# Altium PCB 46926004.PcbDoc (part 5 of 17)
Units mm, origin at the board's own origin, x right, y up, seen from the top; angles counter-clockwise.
Board outline 250 x 200 mm, 6 copper layers (Top Layer, INT1_GND, INT2_SIG, INT3_SIG, INT4_GND, Bottom Layer), stack 1.71 mm thick; 1450 components, 1293 nets, 5656 pads, 2307 vias.
Unrouted connection lines stored in the file: 2.
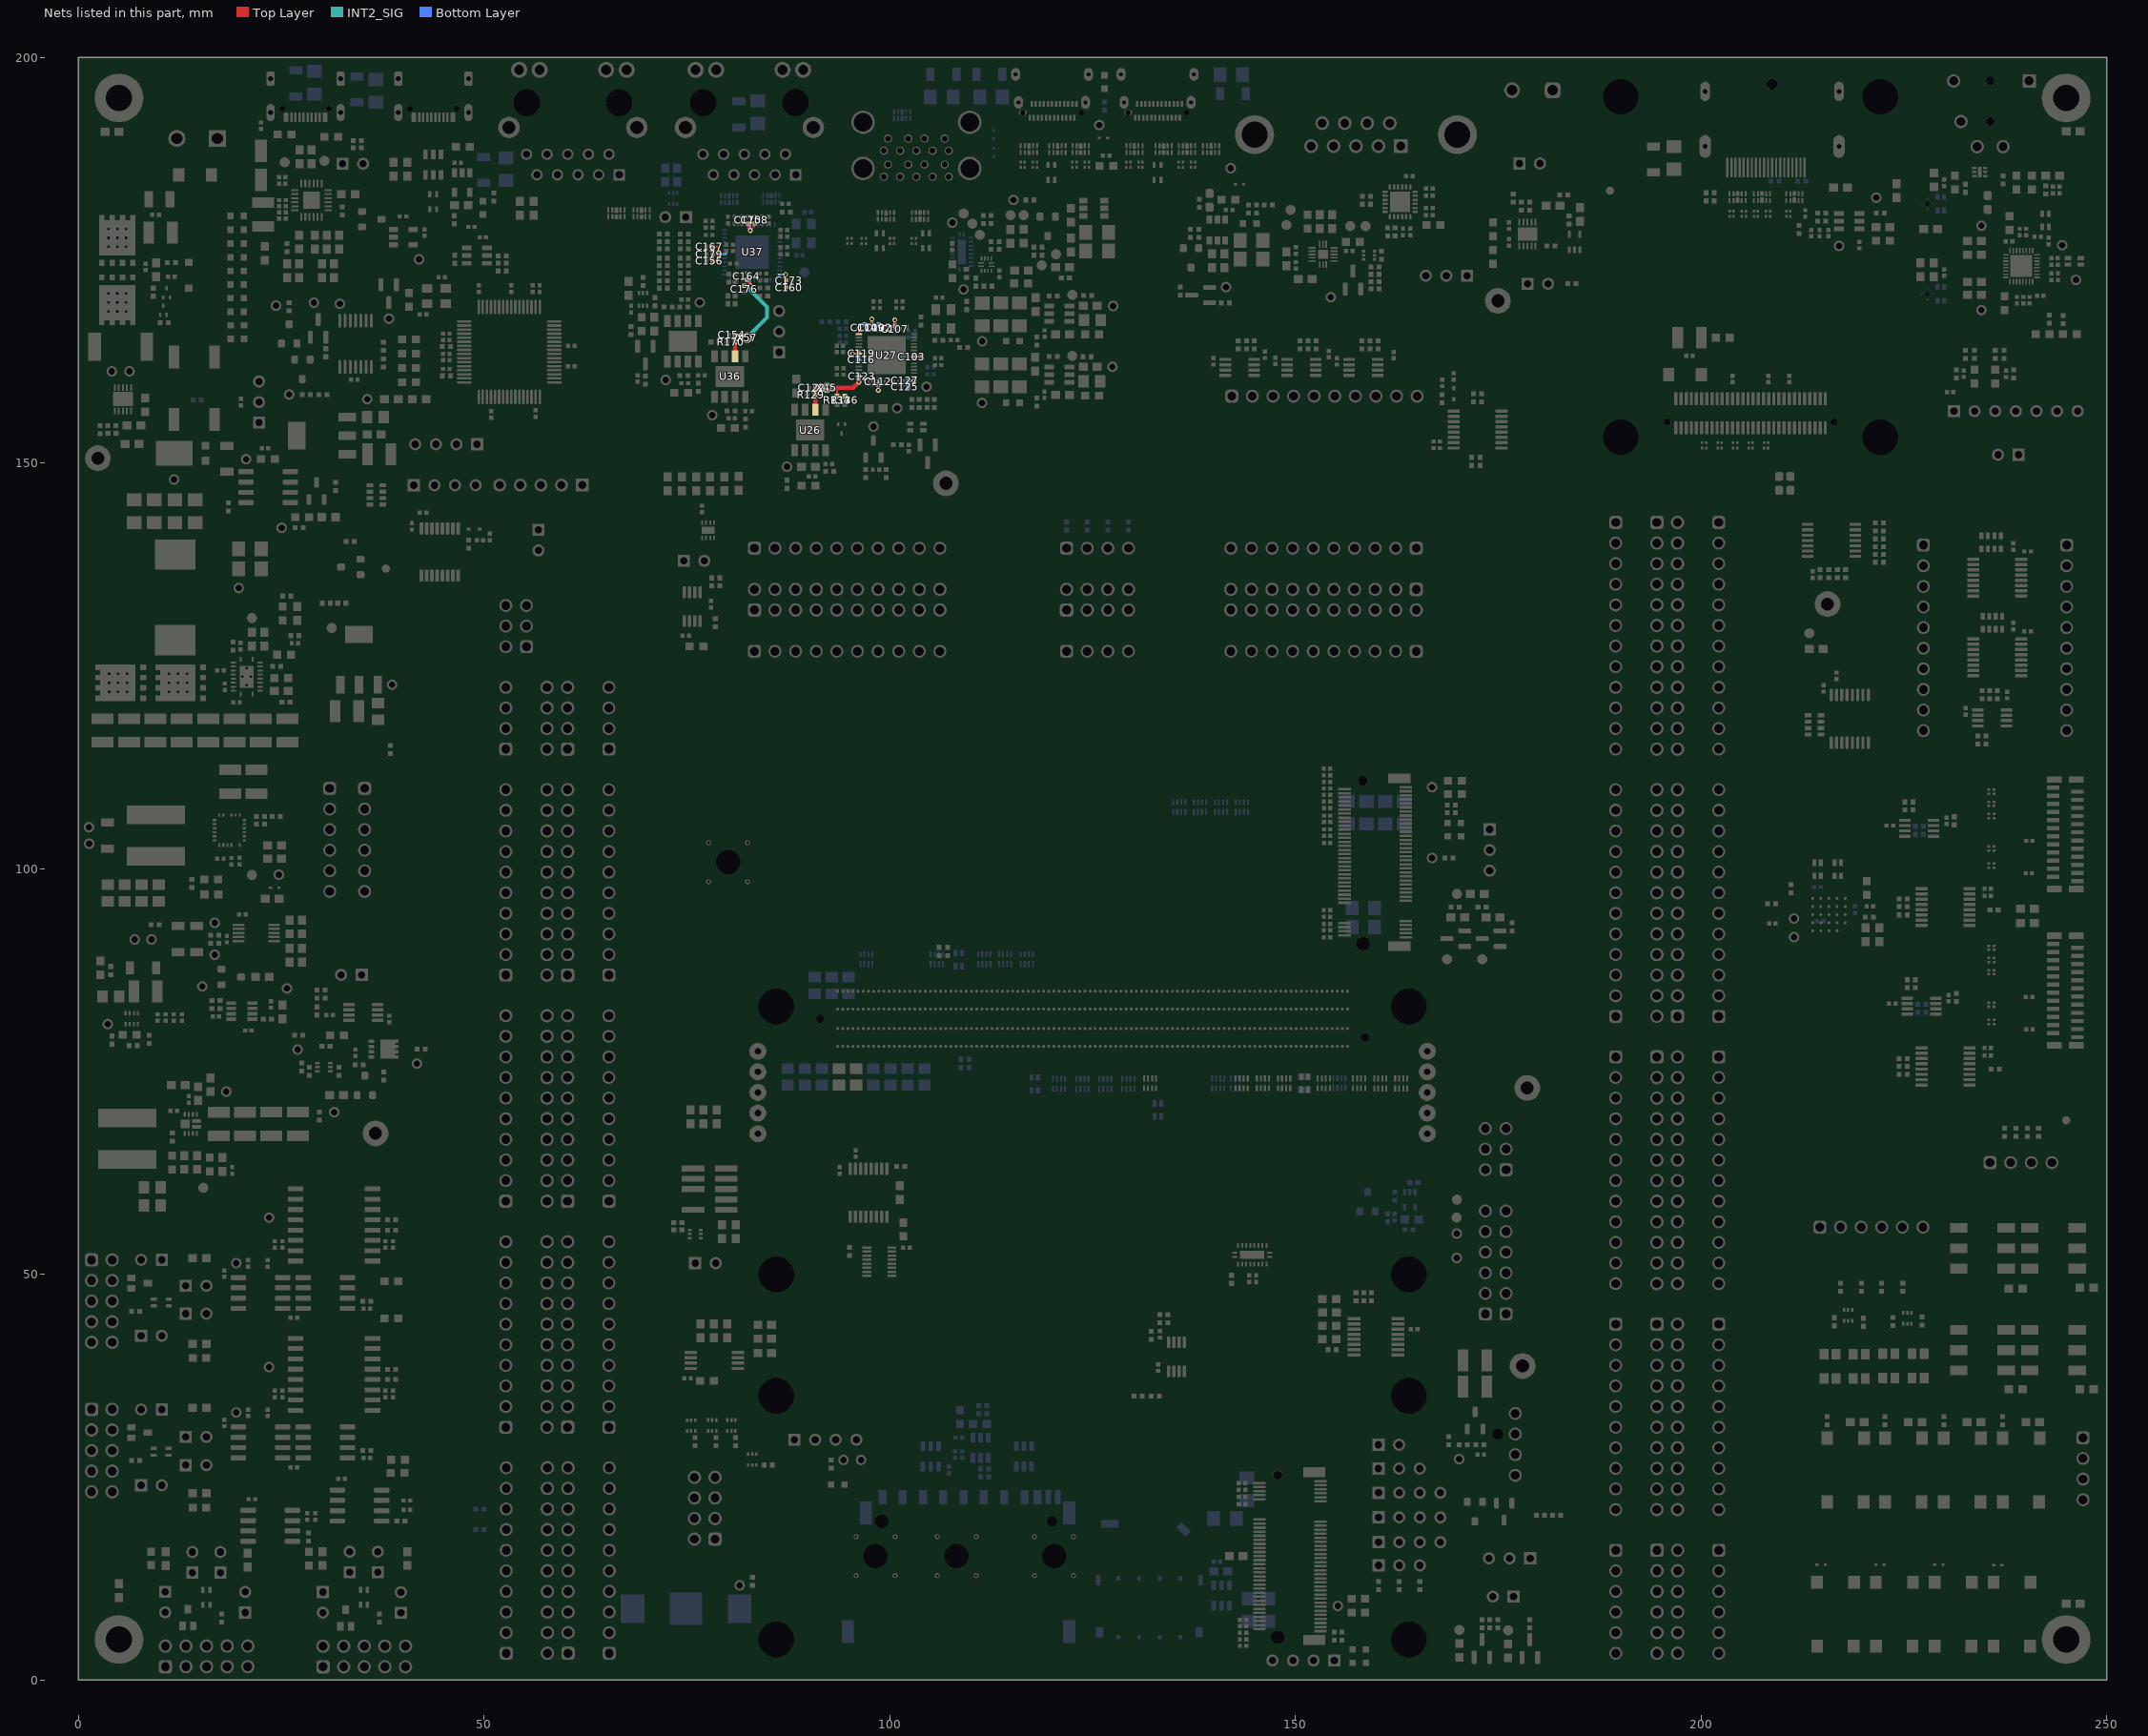
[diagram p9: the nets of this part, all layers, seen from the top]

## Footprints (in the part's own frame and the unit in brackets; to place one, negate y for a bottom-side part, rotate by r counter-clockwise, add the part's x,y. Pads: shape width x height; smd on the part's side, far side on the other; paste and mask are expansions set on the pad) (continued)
"VQFN-20 (3.5X4.5)" [mm] "RGY0020B, 20-VQFN (3.5x4.5)"
  rrect50% 0.25x0.6 smd paste+0 mask+0.051: 1(-0.75,2.15) 10(-0.75,-2.15) 11(0.75,-2.15) 20(0.75,2.15)
  rrect50% 0.6x0.25 smd paste+0 mask+0.051: 2(-1.65,1.75) 3(-1.65,1.25) 4(-1.65,0.75) 5(-1.65,0.25) 6(-1.65,-0.25) 7(-1.65,-0.75) 8(-1.65,-1.25) 9(-1.65,-1.75) 12(1.65,-1.75) 13(1.65,-1.25) 14(1.65,-0.75) 15(1.65,-0.25) 16(1.65,0.25) 17(1.65,0.75) 18(1.65,1.25) 19(1.65,1.75)
  round 0.6 hole 0.3 paste-2539.97 mask+0.051: 21(-0.55,0) 21(0,1.05) 21(0,-1.05) 21(0.55,0)
  rect 1.7x2.7 smd paste-1.337 mask+0.051: 21(0,0)
  silkscreen extent -1.95,-2.45 1.95,2.55, body extent -1.81,-2.31 1.81,2.31, height 1
"VQFN-20 (4.5X2.5)" [mm] "RKS0020A_TEX (2.50?4.50?1) 0.5-mm pitch"
  rrect50% 0.24x0.6 smd paste+0 mask+0.05: 1(-0.25,2.15) 10(-0.25,-2.15) 11(0.25,-2.15) 20(0.25,2.15)
  rrect50% 0.6x0.24 smd paste+0 mask+0.05: 2(-1.15,1.75) 3(-1.15,1.25) 4(-1.15,0.75) 5(-1.15,0.25) 6(-1.15,-0.25) 7(-1.15,-0.75) 8(-1.15,-1.25) 9(-1.15,-1.75) 12(1.15,-1.75) 13(1.15,-1.25) 14(1.15,-0.75) 15(1.15,-0.25) 16(1.15,0.25) 17(1.15,0.75) 18(1.15,1.25) 19(1.15,1.75)
  rect 1x3 smd paste-0.546 mask+0: 21(0,0)
  silkscreen extent -1.42,-2.43 1.42,2.84, body extent -1.3,-2.3 1.3,2.3, height 0.99
"VSONP-8 (5X6)" [mm] "8-PowerTDFN, DQJ0008A"
  rrect20% 0.75x0.675 smd paste+0 mask+0.051: 1(-2.753,1.905) 2(-2.753,0.635) 3(-2.753,-0.635) 4(-2.753,-1.905)
  rrect20% 0.75x0.675 smd paste-2539.97 mask+0.051: 5(2.753,-1.905) 6(2.753,-0.635) 7(2.753,0.635) 8(2.753,1.905)
  round 0.6 hole 0.3: 8(-0.772,1.1) 8(-0.772,-0.005) 8(-0.772,-1.1) 8(0.328,1.1) 8(0.328,-0.005) 8(0.328,-1.1) 8(1.428,-1.1) 8(1.428,-0.005) 8(1.428,1.1)
  rrect5% 4.35x4.485 smd paste-2.272 mask-2.273: 8(0.35,0)
  silkscreen extent -3.35,-2.47 3.4,2.47, body extent -3.1,-2.45 3.16,2.45, height 1.15
WE-CMS_9085 [mm] "Common Mode SMT Bead, body 9.00x8.50mm"
  rect 2.81x1.28 smd: 1(-3.85,2.5) 2(-3.85,-2.5) 3(3.85,-2.5) 4(3.85,2.5)
  silkscreen extent -4.7,-4.45 4.7,4.45, body extent -4.67,-4.25 4.67,4.25, height 4.63
WSON-8(2.1X2.1)_PAD [mm] "8-WFDFN Exposed Pad, 8-WSON (2x2), DSG0008A_TEX"
  rect 0.5x0.25 smd paste+0 mask+0: 1(-0.95,0.75) 2(-0.95,0.25) 3(-0.95,-0.25) 4(-0.95,-0.75) 5(0.95,-0.75) 6(0.95,-0.25) 7(0.95,0.25) 8(0.95,0.75)
  rect 0.9x1.6 smd paste-0.45 mask+0: 9(0,0)
  silkscreen extent -1.1,-1.15 1.07,1.4, body extent -1,-1 1,1, height 0.77
WURTH_9774080360R [mm]
  round 2.2 hole 4.4 unplated: 0(0,0)
  Top Layer circle w1.3: c0,0 r3.05
  Top Layer keep-out circle w0.05: c0,0 r3.9
  Bottom Layer keep-out circle w0.05: c0,0 r2.45
  silkscreen extent -4,-4 4,4, body extent -2.92,-2.95 3.08,3.04, height 8
WURTH_61300411821 [mm] "Socket Header, Pitch 2.54 mm, THT, Vertical, single row, 4p"
  rrect50% 1.6x1.6 hole 1.1: 1(-3.81,0)
  round 1.6 hole 1.1: 2(-1.27,0) 3(1.27,0) 4(3.81,0)
  silkscreen extent -5.46,-1.35 5.46,1.35, body extent -5.33,-1.25 5.33,1.25, height 8.55
WURTH_61300611821 [mm] "Socket Header, Pitch 2.54 mm, THT, Vertical, single row, 6p"
  rrect50% 1.6x1.6 hole 1.1: 1(-6.35,0)
  round 1.6 hole 1.1: 2(-3.81,0) 3(-1.27,0) 4(1.27,0) 5(3.81,0) 6(6.35,0)
  silkscreen extent -8,-1.35 8,1.35, body extent -7.87,-1.25 7.87,1.25, height 8.55
WURTH_61300621821 [mm] "Socket Header, Pitch 2.54 mm, THT, Vertical, dual row, 6p"
  rrect50% 1.6x1.6 hole 1.1: 1(-2.54,-1.27)
  round 1.6 hole 1.1: 2(-2.54,1.27) 3(0,-1.27) 4(0,1.27) 5(2.54,-1.27) 6(2.54,1.27)
  silkscreen extent -4.19,-2.62 4.19,2.62, body extent -4.06,-2.54 4.06,2.54, height 8.45
WURTH_61300821121 [mm] "Pin Header, pitch 2.54 mm, THT, Vertical, dual row, 8p"
  rrect50% 1.65x1.65 hole 1.1: 1(-3.81,-1.27)
  round 1.65 hole 1.1: 2(-3.81,1.27) 3(-1.27,-1.27) 4(-1.27,1.27) 5(1.27,-1.27) 6(1.27,1.27) 7(3.81,-1.27) 8(3.81,1.27)
  silkscreen extent -5.81,-2.62 5.23,2.62, body extent -5.08,-2.54 5.08,2.54, height 8.59
WURTH_61301011821 [mm] "Socket Header, Pitch 2.54 mm, THT, Vertical, single row, 10p"
  rrect50% 1.6x1.6 hole 1.1: 1(-11.43,0)
  round 1.6 hole 1.1: 2(-8.89,0) 3(-6.35,0) 4(-3.81,0) 5(-1.27,0) 6(1.27,0) 7(3.81,0) 8(6.35,0) 9(8.89,0) 10(11.43,0)
  silkscreen extent -13.08,-1.35 13.08,1.35, body extent -12.95,-1.25 12.95,1.25, height 8.55
WURTH_61301021121 [mm] "Pin Header, pitch 2.54 mm, THT, Vertical, dual row, 10p"
  rrect50% 1.65x1.65 hole 1.1: 1(-5.08,-1.27)
  round 1.65 hole 1.1: 2(-5.08,1.27) 3(-2.54,-1.27) 4(-2.54,1.27) 5(0,-1.27) 6(0,1.27) 7(2.54,-1.27) 8(2.54,1.27) 9(5.08,-1.27) 10(5.08,1.27)
  silkscreen extent -6.5,-2.62 6.5,2.62, body extent -6.35,-2.54 6.35,2.54, height 8.59
WURTH_61301211821 [mm] "Socket Header, Pitch 2.54 mm, THT, Vertical, single row, 12p"
  rrect50% 1.6x1.6 hole 1.1: 1(-13.97,0)
  round 1.6 hole 1.1: 2(-11.43,0) 3(-8.89,0) 4(-6.35,0) 5(-3.81,0) 6(-1.27,0) 7(1.27,0) 8(3.81,0) 9(6.35,0) 10(8.89,0) 11(11.43,0) 12(13.97,0)
  silkscreen extent -15.62,-1.35 15.62,1.35, body extent -15.49,-1.25 15.49,1.25, height 8.55
WURTH_61301221121 [mm] "Pin Header, pitch 2.54 mm, THT, Vertical, dual row, 12p"
  rrect50% 1.65x1.65 hole 1.1: 1(-6.35,-1.27)
  round 1.65 hole 1.1: 2(-6.35,1.27) 3(-3.81,-1.27) 4(-3.81,1.27) 5(-1.27,-1.27) 6(-1.27,1.27) 7(1.27,-1.27) 8(1.27,1.27) 9(3.81,-1.27) 10(3.81,1.27) 11(6.35,-1.27) 12(6.35,1.27)
  silkscreen extent -8.35,-2.62 7.77,2.62, body extent -7.62,-2.54 7.62,2.54, height 8.59
WURTH_61302021121 [mm] "Pin Header, pitch 2.54 mm, THT, Vertical, dual row, 20p"
  rrect50% 1.65x1.65 hole 1.1: 1(-11.43,-1.27)
  round 1.65 hole 1.1: 2(-11.43,1.27) 3(-8.89,-1.27) 4(-8.89,1.27) 5(-6.35,-1.27) 6(-6.35,1.27) 7(-3.81,-1.27) 8(-3.81,1.27) 9(-1.27,-1.27) 10(-1.27,1.27) 11(1.27,-1.27) 12(1.27,1.27) 13(3.81,-1.27) 14(3.81,1.27) 15(6.35,-1.27) 16(6.35,1.27) 17(8.89,-1.27) 18(8.89,1.27) 19(11.43,-1.27) 20(11.43,1.27)
  silkscreen extent -13.43,-2.62 12.85,2.62, body extent -12.7,-2.54 12.7,2.54, height 8.59
WURTH_61302421121 [mm] "Pin Header, pitch 2.54 mm, THT, Vertical, dual row, 24p"
  rrect50% 1.65x1.65 hole 1.1: 1(-13.97,-1.27)
  round 1.65 hole 1.1: 2(-13.97,1.27) 3(-11.43,-1.27) 4(-11.43,1.27) 5(-8.89,-1.27) 6(-8.89,1.27) 7(-6.35,-1.27) 8(-6.35,1.27) 9(-3.81,-1.27) 10(-3.81,1.27) 11(-1.27,-1.27) 12(-1.27,1.27) 13(1.27,-1.27) 14(1.27,1.27) 15(3.81,-1.27) 16(3.81,1.27) 17(6.35,-1.27) 18(6.35,1.27) 19(8.89,-1.27) 20(8.89,1.27) 21(11.43,-1.27) 22(11.43,1.27) 23(13.97,-1.27) 24(13.97,1.27)
  silkscreen extent -15.95,-2.62 15.39,2.62, body extent -15.24,-2.54 15.24,2.54, height 8.59
WURTH_691137710002 [mm] "Horizontal Cable Entry with Pressure Clamp, pitch 5mm, 02p"
  rrect50% 1.95x1.95 hole 1.3: 1(-2.5,0.25)
  round 1.95 hole 1.3: 2(2.5,0.25)
  silkscreen extent -5,-3.36 5,3.75, body extent -5,-3.75 5,3.75, height 11.6
XTAL_CX3225 [mm] "KYOCERA"
  rect 1.3x1.05 smd mask+0.08: 1(-1.15,-0.925) 2(1.15,-0.925) 3(1.15,0.925) 4(-1.15,0.925)
  silkscreen extent -2.11,-1.73 0.2,1.47, body extent -1.6,-1.25 1.6,1.25, height 1.05

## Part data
B1 B2 B3 B4 B5 B6 B7 B8: library part "1511-Push Button", "(-25 to 70 DegC) SWITCH TACTILE SPST-NO 0.05A 24V H:4.3mm Switch-PushButton", Mfr=Omron, Supplier Part Number 1=SW1440CT-ND
C1 C2 C18 C19 C20 C23 C40 C43 C205 C265 C266 C272 C273 C274 C275 C278 C281 C284 C293 C331 C332: library part 1607-Cap-1206-10uF/50V, "(-55 to 85 DegC) CAP CER 10UF 50V 10% X5R 1206", Mfr=Samsung, MfrNo=CL31A106KBHNNNE, Supplier Part Number 1=1276-2876-1-ND
C3 C5 C7 C8 C9 C10 C11 C12 C17 C29 C34 C47 C48 C65 C66 C67 C68 C69 C70 C74 C78 C79 C80 C83 C84 C85 C86 C87 C88 C89 C91 C92 C93 C97 C99 C100 C107 C109 C111 C112 C113 C114 C115 C116 C117 C118 C119 C120 C123 C129 C130 C131 C132 C133 C134 C135 C136 C137 C138 C144 C145 C146 C147 C155 C170 C171 C172 C173 C174 C175 C176 C178 C179 C182 C188 C192 C193 C194 C195 C196 C197 C200 C201 C202 C203 C204 C206 C207 C208 C209 C210 C211 C212 C217 C218 C219 C223 C224 C228 C229 C231 C232 C233 C234 C235 C236 C237 C238 C239 C240 C241 C242 C243 C244 C245 C246 C249 C250 C251 C252 C254 C256 C259 C260 C261 C262 C270 C276 C286 C287 C292 C294 C296 C297 C301 C302 C303 C304 C305 C306 C307 C308 C309 C310 C311 C312 C313 C314 C315 C316 C317 C318 C319 C320 C321 C322 C323 C324 C326 C328 C333 C342 C345 C350 C351 C352 C353 C354 C356 C357 C358 C359 C360 C381 C382 C387 C388 C389 C390 C392 C394: library part 1566-Cap-0402-100nF/50V, "(-55 to 125 DegC AEC) Cap Ceramic 0.1uF 50V X7R 10% 0402", Mfr=Murata, MfrNo=GRT155R71H104KE01D, Supplier Part Number 1=490-GRT155R71H104KE01DCT-ND
C4 C13 C14 C15 C52 C53 C54 C55 C56 C57 C58 C59 C60 C61 C62 C63 C64 C285: "(-55 to 85 DegC) CAP CER 22uF 16V X5R 0805", Mfr=Samsung, MfrNo=CL21A226MOQNNNE, Supplier Part Number 1=1276-2909-1-ND
C6 C268: "(-55 to 125 DegC AEC) CAP CER 1.5nF 10% 50V X7R 0402", Mfr="Taiyo Yuden", MfrNo=UMK105B7152KVHF, Supplier Part Number 1=587-6365-1-ND
C16: library part 0665-Cap-0603-470pF/50V, "(-55 to 125 DegC) CAP CER 470PF 50V NP0 0603", Mfr="Samsung Electro-Mechanics America, Inc.", MfrNo=CL10C471JB8NNNC, Supplier Part Number 1=1276-1168-1-ND
C21 C22 C24 C25 C26 C39 C41 C72 C73 C75 C76 C82 C90 C108 C110 C122 C149 C150 C151 C152 C153 C154 C247 C248 C253 C255 C257 C258 C347: library part 2404-Cap-0402-22uF/6.3V, "(-55 to 85 DegC) CAP CER 22UF 6.3V 20% X5R 0402", Mfr=Murata, MfrNo=GRM155R60J226ME11D, Supplier Part Number 1=C415703
C27 C289: library part 1149-Cap-0402-10nF/50V, "(-55 to 125 DegC) Cap Ceramic 10nF 50V X7R 10% 0402", Mfr=Yageo, MfrNo=CC0402KRX7R9BB103, Supplier Part Number 1=311-1349-2-ND
C28 C32 C33 C190 C191 C198 C199 C325 C343 C344: library part 2282-Cap-1206-100uF/10V, "(-55 to 85 DegC) CAP CER 100UF 10V 20% X5R 1206", Mfr=Murata, MfrNo=GRM31CR61A107MEA8L, Supplier Part Number 1=490-GRM31CR61A107MEA8LCT-ND
C30: "(-55 to 85 DegC) CAP CER 10UF 16V 10% X5R 0603", Mfr=Murata, MfrNo=GRM21BR61C106KE15L, Supplier Part Number 1=490-3886-1-ND
C31 C35 C355: "(-55 to 85 DegC) CAP CER 4.7UF 10V 20% X5R 0603", Mfr=Samsung, MfrNo=CL10A475KP8NNNC, Supplier Part Number 1=1276-1044-1-ND
C36 C121 C124 C125 C127: "(-55 to 125 DegC) CAP CER 1000PF 50V 5% NP0 0402", Mfr="Samsung Electro-Mechanics America, Inc", MfrNo=CL05C102JB5NNNC, Supplier Part Number 1=1276-1635-1-ND
C37 C277: "(-55 to 125 DegC AEC) Cap Ceramic 47pF 100V C0G/NP0 5% SMD 0603", Mfr=Samsung, MfrNo=CL10C470JC81PNC, Supplier Part Number 1=1276-6563-1-ND
C38 C339 C340: "(-55 to 125 DegC) CAP CER 220PF 50V 5% NP0 0603", Mfr=Samsung, MfrNo=CL10C221JB8NCNC, Supplier Part Number 1=1276-2234-1-ND
C42 C44 C45 C46: "(-55 to 85 DegC) CAP CER 47UF 10V X5R 0805", Mfr=Murata, MfrNo=GRM21BR61A476ME15L, Supplier Part Number 1=490-9961-1-ND
C49 C141 C142 C158 C160 C161 C164 C165 C166 C167 C168 C169 C213 C214 C295 C298 C334: "(-55 to 85 DegC) CAP CER 1UF 16V 20% X5R 0402", Mfr=Murata, MfrNo=GRM155R61C105MA12D, Supplier Part Number 1=490-14599-1-ND
C50 C98: "Cap 0603 DNP"
C51 C139 C140: library part 1314-Cap-0805-22uF/16V, "(-55 to 85 DegC) CAP CER 22uF 16V X5R 0805", Mfr=Samsung, MfrNo=CL21A226MOQNNNE, Supplier Part Number 1=1276-2909-1-ND
C71 C101 C148 C186 C288 C329 C330 C346: "(-55 to 125 DegC) CAP CER 1000PF 2KV X7R 1206", Mfr="Johanson Dielectrics Inc.", MfrNo=202R18W102KV4E, Supplier Part Number 1=709-1036-1-ND
C77 C81: "(-55 to 125 DegC AEC) CAP CER 20PF 5% 50V C0G/NPO 0402", Mfr=Samsung, MfrNo=CL05C200JB51PNC, Supplier Part Number 1=1276-6601-1-ND
C94 C96 C102 C103 C104 C105 C106 C220 C221 C222 C230 C280 C282 C327 C348 C349: "(-55 to 85 DegC) CAP CER 4.7UF 6.3V 20% X5R 0402", Mfr="Murata Electronics North America", MfrNo=GRM155R60J475ME87D, Supplier Part Number 1=490-5408-1-ND
C95 C225 C226 C227 C271: "(-55 to 85 DegC) CAP CER 2.2UF 10V 20% X5R 0402", Mfr=Yageo, MfrNo=CC0402MRX5R6BB225, Supplier Part Number 1=311-1733-1-ND
C126 C128 C159 C162 C177 C267: "(-55 to 125 DegC AEC) CAP CER 30PF 5% 50V C0G/NPO 0402", Mfr=Murata, MfrNo=GCM1555C1H300JA16D, Supplier Part Number 1=490-GCM1555C1H300JA16DCT-ND
C143 C156 C157 C163 C335 C337 C365 C366 C367 C368 C369 C374 C375 C376 C377 C378 C379 C380 C385 C386 C391 C393: "(-55 to 85 DegC) CAP CER 10UF 6.3V 20% X5R 0402", Mfr=Murata, MfrNo=GRM155R60J106ME44D, Supplier Part Number 1=490-13811-2-ND
C180 C181 C183 C185 C187 C283: "(-55 to 85 DegC) CAP CER 47UF 10V 20% X5R 1206", Mfr=Samsung, MfrNo=CL31A476MPHNNNE, Supplier Part Number 1=1276-3063-1-ND
C184 C189 C336 C338 C341: "(-55 to 125 DegC) CAP CER 470PF 50V NP0 0603", Mfr="Samsung Electro-Mechanics America, Inc.", MfrNo=CL10C471JB8NNNC, Supplier Part Number 1=1276-1168-1-ND
C215 C216 C263 C264: "(-55 to 125 DegC) CAP CER 3600PF 50V C0G/NP0 0603", Mfr=Murata, MfrNo=GRM1885C1H362JA01D, Supplier Part Number 1=490-6386-1-ND
C269: "(-55 to 125 DegC) CAP CER 0.047UF 50V X7R 0603", Mfr="TDK Corporation", MfrNo=C1608X7R1H473K080AA, Supplier Part Number 1=445-1313-1-ND
C279: "(-55 to 125 DegC) CAP CER 560PF 25V C0G/NPO 0603", Mfr=Yageo, MfrNo=CC0603JRNPO8BN561, Supplier Part Number 1=311-3957-1-ND
C290 C291: "(-55 to 125 DegC) CAP CER 330PF 100V 5% NP0 0603", Mfr=Samsung, MfrNo=CL10C331JC8NNNC, Supplier Part Number 1=1276-2274-1-ND
C299 C300: "(-55 to 85 DegC AEC) CAP CER 1UF 50V X7R 0603", Mfr=Murata, MfrNo=GRT188R61H105ME13D, Supplier Part Number 1=490-12331-1-ND
C361 C362 C363 C364 C370 C371 C372 C373 C383 C384: "(-55 to 85 DegC) CAP CER 100UF 6.3V X5R 1206", Mfr=Yageo, MfrNo=CC1206MKX5R5BB107, Supplier Part Number 1=311-1991-1-ND
D1 D31: library part 0434-SMAJ28CA, "(-55 to 150 DegC) TVS DIODE 28VWM 59VC SMA", Mfr=STMicroelectronics, MfrNo=SMAJ28CA-TR, Supplier Part Number 1=497-4620-1-ND
D2 D24 D34: library part "1859-LED Red 0603", "(-30 to 85 DegC) LED RED 0603 99mcd Vf:2.0V", Mfr="Vishay Lite-On", MfrNo=LTST-C190KRKT, Supplier Part Number 1=160-1436-1-ND
D3: library part 2201-SDT15H50P5-13, "(-55 to 150 DegC) DIODE SCHOTTKY 15A 50V Vf:0.3V@1.5A 0.47V@15A SMA", Mfr=Diodes, Supplier Part Number 1=31-SDT15H50P5-13CT-ND
D4 D5 D6 D7 D9 D11 D14 D18 D20 D21 D25 D26 D29 D30 D45 D48 D49: library part "0333-LED Green 0603", "(-40 to 85 DegC) LED GREEN 0603 50mcd", Mfr=Kingbright, MfrNo=APT1608CGCK, Supplier Part Number 1=754-1116-1-ND
D8 D15 D33 D35 D36 D37 D38 D43 D50: library part 1655-D5V0L1B2S9-7, "(-65 to 155 DegC) TVS DIODE Vwm:5V Vcl:14V@6A SOD-923", Mfr=Diodes, Supplier Part Number 1=D5V0L1B2S9-7DICT-ND
D10 D13: library part 1670-BAT54XV2T5G, "(-55 to 125 DegC) DIODE SCHOTTKY 30V 200MA SOD523 / SC79", Mfr="ON Semiconductor", Supplier Part Number 1=BAT54XV2T5GOSCT-ND
D12 D16 D17 D19 D22 D23 D27 D28 D32 D47: library part 0242B-BAT54C, "(-55 to 125 DegC) DIODE SCHOTTKY 30V 200MA SOT23, comm. Cathode", Mfr="ON Semi", MfrNo=BAT54CLT1G, Supplier Part Number 1=BAT54CLT1GOSCT-ND
D39 D40 D41 D42: library part 1775-ASMB-MTB0-0B3A2, "(-40 to 100 DegC) LED RGB DIFFUSED 4PLCC SMD", Mfr=Broadcom, Supplier Part Number 1=516-ASMB-MTB0-0B3A2CT-ND
D44: library part 0210-BZX84-C12, "(-65 to 150 DegC) DIODE ZENER 12V 225MW SOT23-3", Mfr="On Semi", MfrNo=BZX84C12LT1G, Supplier Part Number 1=BZX84C12LT1GOSCT-ND
D46: library part 1159-1N4148W, "(-55 to 150 DegC) DIODE GEN PURP 100V 300MA SOD123", Mfr=Diodes, MfrNo=1N4148W-7-F, Supplier Part Number 1=1N4148W-FDICT-ND
F1: library part "2200-Fuse 15A 1206 Slow", "(-55 to 90 DegC) FUSE BOARD MOUNT 15A 63VDC SLOW", Mfr=Schurter, MfrNo=3413.0330.22, Supplier Part Number 1=693-3413.0330.22
F2: library part "1336-Fuse 7A Slow", "(-55 to 125 DegC) FUSE SLOW 63VDC 6A 1206 14.5mohm", Mfr=Bel, MfrNo=0685T6000-01, Supplier Part Number 1=507-2300-1-ND
FID1 FID2 FID3 FID4 FID5 FID6: library part 0000-Fiducial-round, "Fiducial round d=1.0mm"
H1 H2 H3 H4: library part 000-Hole-125mil
J1 J2 J3 J5 J7 J9 J12: library part "2203-Conn-Hdr 2x10 2.54MM", "(-40 to 105 DegC) CONN HEADER MALE VERT 2x10 20POS 2.54MM TH", Mfr="Wurth Electronics", Supplier Part Number 1=732-5301-ND
J1A J1B J2A J2B J3A J3B J5A J5B J7A J7B J9A J9B J12A J12B J13 J60 J61: library part "2202-Conn-Hdr 1x10 2.54MM F", "(-40 to 105 DegC) CONN HEADER FEMALE VERT 1x10 10POS 2.54MM TH", Mfr="Wurth Electronics", Supplier Part Number 1=732-2859-ND
J4 J6 J8: library part "2206-Conn-Hdr 2x12 2.54MM", "(-40 to 105 DegC) CONN HEADER MALE VERT 2x12 24POS 2.54MM TH", Mfr="Wurth Electronics", Supplier Part Number 1=710-61302421121
J4A J4B J6A J6B J8A J8B: library part "2221-Conn-Hdr 1x12 2.54MM F", "(-40 to 105 DegC) CONN HEADER FEMALE VERT 1x12 12POS 2.54MM TH", Mfr="Wurth Electronics", Supplier Part Number 1=710-61301211821
J10 J11 J19: library part "2532-Conn-Hdr 2x4 2.54MM", "(-40 to 105 DegC) CONN HEADER MALE VERT 2x4 8POS 2.54MM TH", Mfr="Wurth Electronics", Supplier Part Number 1=732-5296-ND
J10A J10B J11A J11B J50 J53: library part "2191-Conn-Hdr 1x4 2.54MM F", "(-40 to 125 DegC) CONN HEADER FEMALE 1x4 4POS 2.54MM TH", Mfr="Wurth Electronics", Supplier Part Number 1=732-61300411821-ND
J14: library part "2266-Conn-Hdr 2x6 2.54MM", "(-40 to 105 DegC) CONN HEADER MALE VERT 2x6 12POS 2.54MM TH", Mfr="Wurth Electronics", Supplier Part Number 1=732-5297-ND
J14A J14B J15 J16 J55 J94 J96: library part "2189-Conn-Hdr 1x6 2.54MM F", "(-40 to 125 DegC) CONN HEADER FEMALE 1x6 6POS  2.54MM TH", Mfr="Wurth Electronics", Supplier Part Number 1=732-61300611821-ND
J17: library part "1610-Conn 2-POS R/A", "(-40 to 100 DegC) TERM BLOCK HDR 2POS R/A 90DEG TH 5MM 300V/16A", Mfr="Phoenix Contact", Supplier Part Number 1=277-14388-ND
J18: "(-40 to 85 DegC) CONN HDR VERT 1x2 2pos 2.54mm 0.1in Gold no-shroud", Mfr="Amphenol FCI", MfrNo=67996-200HLF, Supplier Part Number 1=609-5098-1-ND
J20: library part "2094-Conn-Hdr 1x2 2POS 5MM SCREW TERM", "(-30 to 120 DegC) CONN TERM BLK 2POS SIDE ENTRY 5MM SCREW 16A 300V", Mfr="Wurth Electronics", Supplier Part Number 1=732-10955-ND
J21 J87 J91: library part "2539-Conn-Hdr-1x3 TH Vert", "(-65 to 125 DegC) CONN HDR VERT 3x1 3pos 2.54mm 0.1in Gold no-shroud", Mfr="Amphenol ICC / FCI", Supplier Part Number 1=649-68001-203HLF
J22 J28 J31 J51 J88: "Header, 2-Pin"
J23 J65: library part 1660-Conn-USB-Type-C, "(-40 to 85 DegC) Conn USB TYPE C RA, 24 (16+8 Dummy) Position, SMT/TH", Mfr="Global Connector Technology", Supplier Part Number 1=2073-USB4105-GF-A-120CT-ND
J24 J26 J37 J38 J40 J54 J57: "Header, 4-Pin"
J25: "Header, 5-Pin"
J27: library part 2274-CONN-DISPLAY-PORT, "(-20 to 85 DegC) CONN RCPT DISPLAYPORT 20P SMD RA/TH", Mfr=Molex, MfrNo=47272-0001, Supplier Part Number 1=538-47272-0001
J29 J45 J49 J58 J63 J64 J66 J68 J73 J74 J75 J76 J79 J80 J81 J82 J85 J86 J89 J90 J92: library part "1250-Conn-Hdr-1x2 TH Vert", "(-40 to 85 DegC) CONN HDR VERT 1x2 2pos 2.54mm 0.1in Gold no-shroud", Mfr="Amphenol FCI", Supplier Part Number 1=609-5098-1-ND
J30: library part 2184-Conn-SD, "(-40 to 85 DegC) CONN SD CARD PUSH-PULL R/A, OPEN", Mfr="Same Sky", Supplier Part Number 1=2223-SD-4-BCT-ND
J32 J72: library part 1512-Conn-USB-Type-C, "(-40 to 85 DegC) Conn USB TYPE C RA SMT", Mfr="Amphenol Communications Solutions", Supplier Part Number 1=12401826E412ACT-ND
J33: library part 1820-Conn-USB3-2x-RA, "(-40 to 85 DegC) Conn USB 3.1 Type A R/A TH", Mfr="Amphenol Commercial", Supplier Part Number 1=GSB4112312HR-ND
J34 J36: library part 1380-Conn-RJ45-GBe, "(-40 to 85 DegC) CONN MAGJACK 1PORT 1000 BASE-T Isolated Taps", Mfr=Pulse, Supplier Part Number 1=1840-1005-ND
J35 J41 J52 J62: "Header, 3-Pin"
J39: library part 2186-Conn-M2-KeyB, "(-40 to 80 DegC) CONN M2 M.2 Key B 67pos H=2.75mm Gold", Mfr="Amphenol Commercial", Supplier Part Number 1=523-MDT275B03001
J42: "(-40 to 85 DegC) CONN MICRO SIM CARD PUSH-PULL", Mfr="Molex, LLC", MfrNo=0787231001, Supplier Part Number 1=WM9259CT-ND
J43: library part 2461-Conn-M2-KeyM_4.2mm, "(-40 to 85 DegC) CONN M.2 KEYM FMALE 67POS 0.020 GOLD 4.2MM HEIGHT", Mfr="Amphenol Communications Solutions", Supplier Part Number 1=649-MDT420M01501
J44: library part 1462-Conn-SelfMate-60pin, "(-55 to 125 DegC) CONN SELF-MATE 60POS SMD GOLD", Mfr=Samtec, Supplier Part Number 1=612-LSS-130-03-L-DV-A-K-TRCT-ND
J46: library part 1840-Conn-Audio-Jack-5pos-3.5mm, "(-20 to 85 DegC) CONN JACK STEREO 3.5MM 5pos TipSwitch TH R/A", Mfr="Same Sky", Supplier Part Number 1=CP-43515TS-ND
J47 J48: library part "2193-Conn-Hdr 2x3 2.54MM F", "(-40 to 125 DegC) CONN HEADER FEMALE 2x3 6POS 2.54MM TH", Mfr="Wurth Electronics", Supplier Part Number 1=732-61300621821-ND
J56: library part "2220-Conn-Hdr 4POS 2.54MM", "(-40 to 80 DegC) CONN HEADER VERT 4POS 2.54MM - 1 Wall Shrouded", Mfr=Molex, MfrNo=47053-1000, Supplier Part Number 1=WM4330-ND
J59: "(-55 to 125 DegC) CONN HEADER VERT 9POS 2x5 1.27MM JTAG", Mfr=Samtec, MfrNo=FTSH-105-01-L-DV-007-K, Supplier Part Number 1=SAM9438-ND
J67: library part "0760-Conn-DSUB9 Male R/A", "(-55 to 105 DegC) CONN D-SUB PLUG 9POS R/A SOLDER Male", Mfr="Assmann WSW Components", MfrNo="A-DS 09 A/KG-T2S", Supplier Part Number 1=AE10968-ND
J69: "Header, 7-Pin"
J70 J71: library part 1461-Conn-FFC-24pin-0.5mm-Vert, "(-40 to 85 DegC) CONN FFC VERT 24POS 0.50MM SMD", Mfr=Hirose, Supplier Part Number 1=H125143CT-ND
J77 J78 J83 J84: library part "2237-Conn-Hdr 2x10 2.54MM", "(-40 to 105 DegC) CONN HEADER MALE VERT 2x5 10POS 2.54MM TH", Mfr="Wurth Electronics", Supplier Part Number 1=732-2672-ND
J95 J97: library part "2368-Conn-POGO 1x5 2.54MM", "CONN SPRING PISTON 5POS PCB 2.54MM TH", Mfr=Mill-Max, Supplier Part Number 1=ED8201-05-ND
JP1 JP2 JP3 JP4: library part 000-Jumper-Short, "Jumper Wire"
L1: library part 2226-Ind-9x8.5-83ohm/21A-Choke, "(-40 to 125 DegC AEC) CMC Choke 21A 83OHM 9x8.5x4.8mm DCR = 3mohm", Mfr="Wurth Electronics", MfrNo=7427523, Supplier Part Number 1=710-7427523
L4 L6: library part 1845-Ind-8x8x5-4.7uH/11A, "(-40 to 85 DegC) FIXED IND 4.7UH 11A Is:13A 14 mohm typ, 15.4 moh max SMD 8.4x8x5 full-shield", Mfr="Eaton Bussmann", Supplier Part Number 1=283-EXL1V0705-4R7-RCT-ND
L5: "(-40 to 125 DegC) FIXED IND 1UH I:5.5A Isat:6.5A 32mohm max 26mohm typ, full-shield SMD 1210", Mfr=Bourns, MfrNo=SRP3212-1R0M, Supplier Part Number 1=118-SRP3212-1R0MCT-ND
L9: "(-50 to 150 DegC) FIXED IND 2.2UH 22A 4.2 mOHM 13.5x12.5x6.4mm", Mfr=Bourns, MfrNo=SRP1265A-2R2M, Supplier Part Number 1=652-SRP1265A-2R2M
L10 L11 L12 L43 L45: "(-55 to 125 DegC) FERRITE BEAD 5 OHM @ 100MHz 0402 0.5A DCR:80mohm", Mfr=Murata, MfrNo=BLM15BB050SN1D, Supplier Part Number 1=490-5185-1-ND
L13 L15 L16 L17 L18 L19 L20 L21 L26 L31 L32 L33 L41 L42 L46 L47 L48 L49 L55 L56 L57 L60 L61 L62 L63 L66 L71 L72 L75 L78 L79 L80 L91 L92: "(-55 to 125 DegC) FERRITE BEAD 330 OHM 0603 1.7A 80mohm, typ 48mohm", Mfr="TDK Corporation", MfrNo=MPZ1608S331ATA00, Supplier Part Number 1=445-5221-1-ND
L14 L30 L36 L39 L99: library part 0277-Ind-2x1.2-90ohm/0.4A-Choke, "(-40 to 125 DegC) INDUCTOR COMMON MODE 90 OHM 0.4A 0.3ohm", Mfr="Bourns Inc.", MfrNo=SRF2012-900YA, Supplier Part Number 1=SRF2012-900YACT-ND
L22 L23 L28 L29 L34 L35 L37 L38 L50 L51 L52 L53 L54 L76 L81 L82 L83 L84 L85 L86 L87 L88 L89 L90 L94 L95 L96 L97 L100 L101 L102 L103: library part 1371-Ind-0.8x0.6-12ohm/0.1A-Choke, "(-40 to 85 DegC) Ind CMC Choke 12 Ohm 0.1A 1ohm 0.85x0.65x0.5mm", Mfr=Panasonic, MfrNo=EXC-14CH120U, Supplier Part Number 1=P19438CT-ND
L58 L59 L73 L74: library part 1055-Ind-2x1.2-220ohm/0.4A-Choke, "(-40 to 125 DegC) INDUCTOR COMMON MODE 220 OHM 0.3A 0.4ohm", Mfr="Bourns Inc.", MfrNo=SRF2012-221YA, Supplier Part Number 1=SRF2012-221YACT-ND
L77: "(-55 to 125 DegC AEC) FERRITE BEAD 42ohm 10A 0.75mohm 3x3mm SMD", Mfr="Laird Steward", MfrNo=35F0121-0SR-10, Supplier Part Number 1=240-2520-1-ND
LBL1: library part 000-Label-0.25x0.9IN, "Label for Toradex serial number label 0.25x0.9 inch"
M1: library part 2421-Conn-Toradex-Aquila, "(-55 to 125 DegC) CONN AcceleRate HD APM6 0.635MM 400POS SMD HIGH DENSITY ARRAY, 5MM STACK HEIGHT (UN-BALLED)", Mfr=Samtec
ME1 ME2 ME3 ME4: library part 0989-Post-M3-8mm, "(-55 to 150 DegC) ROUND STANDOFF M3X0.5 STEEL 8MM For Apalis", Mfr="Wurth Electronics Inc.", Supplier Part Number 1=732-5275-1-ND
ME5 ME6 ME7 ME8 ME9 ME10 ME11 ME12: "(-55 to 155 DegC) ROUND STANDOFF M3X0.5 BRASS 5MM", Mfr=Sinhoo, MfrNo=SMTSO3050CTJ, Supplier Part Number 1=C2915636
ME13 ME14 ME15 ME18: library part 1855-Post-M2-0.5mm, "(-55 to 155 DegC) ROUND STANDOFF M2X0.4 STEEL 0.5MM", Mfr="Wurth Electronics", Supplier Part Number 1=732-9774005243RCT-ND
MP1 MP2 MP3 MP4 MP5 MP6 MP7 MP8 MP9 MP10: library part 1476-Bumper-10mmD-6mmH, "(-40 to 85 DegC) Bumper Polyurethane, D: 9.5mm, H: 6.3mm, adhesive", Mfr=3M, Supplier Part Number 1=SJ5749-0-ND
Q1 Q2 Q23: library part 2195-CSD18511Q5A, "(-55 to 150 DegC) MOSFET N-CH 40V 27A Vth:1.8V Ron typ:3.5mohm@4.5V Vgsm:2.45V 8-VSONP (5x6)", Mfr="Texas Instruments", MfrNo=CSD18511Q5AT, Supplier Part Number 1=595-CSD18511Q5AT
Q3: library part 1858-DMP26M7UFG-7, "(-55 to 150 DegC) MOSFET P-CH 20V 18A 4.2mohm@4.5V 7mohm@1.8V Vgsm:10V 3x3mm POWERDI3333", Mfr=Diodes, Supplier Part Number 1=DMP26M7UFG-7DICT-ND
Q4 Q5 Q6 Q8 Q21 Q28 Q29: library part 0761-FDV301N, "(-55 to 155 DegC) MOSFET N-CH 25V 220MA SOT-23 Vth:1.1V Ron typ:4ohm@3V Vgsm:8V", Mfr="Fairchild/ON Semiconductor", Supplier Part Number 1=FDV301NCT-ND
Q7 Q30: library part 1674-NTZD3155CT1G, "(-40 to 85 DegC) MOSFET N/P-CH 20V 0.54/0.43A Vgs:1V SOT-563", Mfr="ON Semiconductor", Supplier Part Number 1=NTZD3155CT1GOSCT-ND
Q9 Q10 Q11 Q12 Q15 Q18 Q19 Q31 Q32: library part 1146-NTZD3154NT1G, "(-55 to 150 DegC) MOSFET 2N-CH (dual) 20V 0.54A SOT-563 1.6x1.6mm Vth:1V Ron typ:400m@4.5V, 500m@2.5V, 700m@1.8V", Mfr="ON Semiconductor", MfrNo=NTZD3154NT1G, Supplier Part Number 1=NTZD3154NT1GOSCT-ND
Q13: library part 0186-DMP3099L, "(-55 to 150 DegC) MOSFET P-CH 30V 3.8A 65mohm SOT23", Mfr="Diodes Incorporated", MfrNo=DMP3099L-7, Supplier Part Number 1=DMP3099L-7DICT-ND
Q14 Q16 Q25: library part 1857-MMBT5551M3T5G, "(-55 to 150 DegC) TRANS NPN 160V 60mA 1.2x1.2 SOT723", Mfr="ON Semiconductor", Supplier Part Number 1=MMBT5551M3T5GOSCT-ND
Q17: library part 0910-IRLML0040TRPBF, "(-55 to 150 DegC) MOSFET N-CH 40V 3.6A SOT-23-3 Ron typ 60mohm@5V, ---@3V", Mfr="Infineon Technologies", MfrNo=IRLML0040TRPBF, Supplier Part Number 1=IRLML0040TRPBFCT-ND
Q22: library part 2196-CSD18503Q5A, "(-55 to 150 DegC) MOSFET N-CH 40V 19A Vth:1.8V Ron typ:4.3mohm@10V Vgsm:2.45V 8-VSONP (5x6)", Mfr="Texas Instruments", Supplier Part Number 1=595-CSD18503Q5A
Q24: "(-55 to 150 DegC) MOSFET 2P-CH 30V 9.2A 8SO", Mfr="Infineon Technologies", MfrNo=IRF9358TRPBF, Supplier Part Number 1=942-IRF9358TRPBF
Q26 Q27: library part 0030-2N7002, "(-55 to 150 DegC AEC) MOSFET N-CH SGL 60V SOT-23 0.3A 1.3ohm@5V", Mfr=NXP, MfrNo=2N7002P,215, Supplier Part Number 1=568-5818-1-ND
R1 R389: "(-55 to 155 DegC AEC) RES 887K OHM 1% 1/16W 100ppm 0402", Mfr="Stackpole Electronics", MfrNo=RMCF0402FT887K
R2 R6 R44 R49 R142 R143 R309: "(-55 to 155 DegC) RES SMD 24.9K OHM 1% 1/10W 0603 100ppm", Mfr="Stackpole Electronics", MfrNo=RMCF0603FT24K9, Supplier Part Number 1=RMCF0603FT24K9CT-ND
R3 R7 R46 R303 R304 R310 R311 R323 R326 R336: "(-55 to 155 DegC) RES SMD 20K 1% 1/10W 0603 100ppm", Mfr=Bourns, MfrNo=CR0603-FX-2002ELF, Supplier Part Number 1=CR0603-FX-2002ELFCT-ND
R4 R19 R20 R29 R30 R31 R36 R45 R55 R86 R87 R89 R90 R104 R114 R129 R134 R165 R166 R182 R193 R195 R198 R203 R283 R285 R335 R378 R379: "(-55 to 155 DegC AEC) RES 27K OHM 1% 1/16W 100ppm 0402", Mfr="Stackpole Electronics", MfrNo=RMCF0402FT27K0, Supplier Part Number 1=RMCF0402FT27K0CT-ND
R5 R9 R35 R37 R53 R56 R57 R63 R115 R256 R257 R259 R261 R263 R270 R289 R290 R307 R317 R344 R360 R361 R362 R366 R368 R369 R370 R374 R375 R376 R377 R391 R393 R394 R399 R404 R434: "(-55 to 155 DegC) RES 100K OHM 1/16W 1% 0402 SMD", Mfr=Yageo, MfrNo=RC0402FR-07100KL, Supplier Part Number 1=311-100KLRCT-ND
R8: "(-55 to 170 DegC AEC) RES 0.003 OHM 1% 2W 2512 50ppm", Mfr=Bourns, MfrNo=CRF2512-FZ-R003ELF, Supplier Part Number 1=652-CRF2512FZR003ELF
R10 R27 R43 R50 R58 R59 R67 R68 R95 R108 R113 R116 R117 R118 R122 R135 R136 R137 R152 R154 R162 R169 R171 R173 R181 R186 R188 R189 R215 R218 R230 R231 R238 R266 R268 R269 R271 R273 R274 R279 R280 R281 R282 R313 R314 R327 R332 R333 R334 R343 R345 R352 R358 R382 R383 R384 R385 R408 R418 R419 R432 R453 R454 R455 R456 R457 R459 R460 R470 R473 R474 R476: "(-55 to 155 DegC AEC) RES 10K OHM 1% 1/16W 100ppm 0402", Mfr="Stackpole Electronics", MfrNo=RMCF0402FT10K0, Supplier Part Number 1=RMCF0402FT10K0CT-ND
R11 R15 R17 R28 R32 R33 R38 R54 R64 R110 R131 R183 R185 R194 R199 R217 R221 R222 R223 R228 R232 R233 R234 R251 R252 R287 R301 R308 R329 R331 R337 R339 R341 R354 R355 R359 R367 R406 R435 R436 R437 R438 R447 R448 R449 R463 R464: "(-55 to 155 DegC) RES 0.0 OHM 1/10W JUMP 0603", Mfr=Samsung, MfrNo=RC1608J000CS, Supplier Part Number 1=1276-3510-1-ND
R12 R69 R70 R77 R100 R126 R127 R248 R363 R371: "(-55 to 155 DegC AEC) RES 200K OHM 1% 1/16W 100ppm 0402", Mfr="Stackpole Electronics", MfrNo=RMCF0402FT200K, Supplier Part Number 1=RMCF0402FT200KCT-ND
R13 R14 R24 R26 R40 R60 R71 R72 R73 R74 R78 R79 R83 R102 R103 R119 R144 R145 R172 R174 R239 R249 R250 R272 R312 R364 R365 R372 R373 R387 R396 R402 R403 R430 R431 R445 R446 R465: "(-55 to 155 DegC) RES 4.70K OHM 1/16W 1% 0402 100ppm", Mfr=Yageo, MfrNo=RC0402FR-074K7L, Supplier Part Number 1=311-4.7KLRCT-ND
R16 R18 R34 R96 R106 R107 R109 R124 R138 R139 R180 R191 R224 R225 R226 R229 R235 R236 R237 R253 R254 R284 R286 R288 R320 R321 R328 R330 R338 R342 R346 R386 R390 R407 R439: "RES 0603"
R21 R25 R348 R349 R353: "(-55 to 155 DegC) RES 10 OHM 1/16W 1% 0402 SMD", Mfr="Rohm Semiconductor", MfrNo=MCR01MRTF10R0, Supplier Part Number 1=RHM10.0CDCT-ND
R22 R23 R51: "(-55 to 150 DegC) RES CURRENT SENSE .010 OHM 1W 1% 50ppm", Mfr=Ohmite, MfrNo=MCS1632R010FER, Supplier Part Number 1=MCS1632R010FERCT-ND
R39: "RES CURRENT SENSE .010 OHM 1W 1% 50ppm", Mfr=Ohmite, MfrNo=MCS1632R010FER, Supplier Part Number 1=MCS1632R010FERCT-ND
R41 R42 R48: "(-55 to 155 DegC) RES SMD 220K OHM 1% 1/10W 0603", Mfr=Yageo, MfrNo=RC0603FR-07220KL, Supplier Part Number 1=311-220KHRCT-ND
R47 R324 R452: "(-55 to 155 DegC AEC) RES 15K OHM 1% 1/16W 100ppm 0402", Mfr="Stackpole Electronics", MfrNo=RMCF0402FT15K0, Supplier Part Number 1=RMCF0402FT15K0CT-ND
R52 R75 R76 R88 R99 R175 R187 R196 R197 R202 R204 R227 R264 R265 R409 R410 R411 R412 R413 R414 R426 R427 R442 R443 R468 R469 R471 R472 R477 R478: "(-55 to 155 DegC AEC) RES 1.87K OHM 1% 1/16W 100ppm 0402", Mfr="Stackpole Electronics", MfrNo=RMCF0402FT1K87, Supplier Part Number 1=RMCF0402FT1K87CT-ND
R61 R84 R325: "(-55 to 155 DegC) RES 300K OHM 1/10W 1% 0603 SMD", Mfr=Yageo, MfrNo=RC0603FR-07300KL, Supplier Part Number 1=311-300KHRCT-ND
R62 R65 R66 R125 R128 R140 R141 R149 R150 R151 R158 R161 R164 R167 R168 R184 R200 R219 R322 R392 R417 R450 R451 R475: "RES 0402"
R80 R81 R315 R388 R405: "(-55 to 155 DegC) RES 5.1K OHM 1/10W 1% 0603 SMD", Mfr=Rohm, MfrNo=MCR03ERTF5101, Supplier Part Number 1=RHM5.10KCFCT-ND
R82 R120 R148 R179 R267 R319 R397 R398: "(-55 to 155 DegC) RES SMD 1M OHM 5% 0.25W 10ppm 1206", Mfr="TE Connectivity", MfrNo=CRGCQ1206J1M0, Supplier Part Number 1=A130195CT-ND
R85 R97 R98 R190 R241 R243 R245 R247 R275 R276 R277 R278 R440 R441 R444: "(-55 to 155 DegC AEC) RES 86.6K OHM 1% 1/16W 100ppm 0402", Mfr="Stackpole Electronics", MfrNo=RMCF0402FT86K6, Supplier Part Number 1=RMCF0402FT86K6CT-ND
R91 R132 R306: "(-55 to 155 DegC AEC) RES 12K OHM 1% 1/16W 100ppm 0402", Mfr="Stackpole Electronics", MfrNo=RMCF0402FT12K0, Supplier Part Number 1=RMCF0402FT12K0CT-ND
R92 R93 R94 R458 R467: "(-55 to 155 DegC AEC) RES 1M OHM 1% 1/16W 100ppm 0402", Mfr="Stackpole Electronics", MfrNo=RMCF0402FT1M00, Supplier Part Number 1=RMCF0402FT1M00CT-ND
R101 R112: "(-55 to 155 DegC) RES SMD 2K OHM 1% 1/10W 0603 100ppm", Mfr=Yageo, MfrNo=RC0603FR-072KL, Supplier Part Number 1=311-2.00KHRCT-ND
R105 R111 R121 R123 R159 R160 R210 R213 R220 R298 R350 R356 R357 R380 R381 R395 R400 R401 R433: "(-55 to 155 DegC AEC) RES 120 OHM 1% 1/16W 100ppm 0402", Mfr="Stackpole Electronics", MfrNo=RMCF0402FT120R, Supplier Part Number 1=RMCF0402FT120RCT-ND
R130: "(-55 to 155 DegC) RES 56K OHM 1/10W 1% 0603", Mfr="Samsung Electro-Mechanics America, Inc", MfrNo=RC1608F563CS, Supplier Part Number 1=1276-4816-1-ND
R133 R291 R292 R316 R351: "(-55 to 155 DegC AEC) RES 1K OHM 1% 1/16W 100ppm 0402", Mfr="TE Connectivity", MfrNo=CRGCQ0402F1K0, Supplier Part Number 1=A129627CT-ND
R146 R147 R177 R178 R240 R242 R244 R246 R255 R258 R260 R262: "(-55 to 155 DegC) RES 510 OHM 1/10W 1% 0603 SMD", Mfr=Yageo, MfrNo=RC0603FR-07510RL, Supplier Part Number 1=311-510HRCT-ND
R153 R155 R157 R163 R170: "(-55 to 155 DegC) RES SMD 2.49K OHM 1% 1/16W 0402 100ppm", Mfr=Yageo, MfrNo=RC0402FR-072K49L, Supplier Part Number 1=311-2.49KLRCT-ND
R156: "(-55 to 155 DegC) RES 5.76K OHM 1/16W 1% 0402 SMD", Mfr="Stackpole Electronics", MfrNo=RMCF0402FT5K76, Supplier Part Number 1=RMCF0402FT5K76CT-ND
R176: "(-55 to 155 DegC AEC) RES SMD 11K OHM 1% 1/16W 0402 100ppm 0402", Mfr=Yageo, MfrNo=AC0402FR-0711KL, Supplier Part Number 1=YAG3439CT-ND
R192 R212 R214 R297 R299 R300 R302 R340: "RES 0.0 OHM 1/10W JUMP 0603", Mfr=Samsung, MfrNo=RC1608J000CS, Supplier Part Number 1=1276-3510-1-ND
R205 R206 R207 R208 R293 R294 R295 R296: "(-55 to 155 DegC) RES SMD 60.4 OHM 1% 1/10W 0603", Mfr=Bourns, MfrNo=CR0603-FX-60R4ELF, Supplier Part Number 1=652-CR0603FX-60R4ELF
R216: "(-55 to 155 DegC) RES 2.20K OHM 1/10W 1% 0603 SMD", Mfr=Yageo, MfrNo=RC0603FR-072K2L, Supplier Part Number 1=311-2.20KHRCT-ND
R305: "(-55 to 155 DegC) RES SMD 240 OHM 1% 1/16W 0402", Mfr=Yageo, MfrNo=RC0402FR-07240RL, Supplier Part Number 1=311-240LRCT-ND
R318 R347: "(-55 to 155 DegC AEC) RES 330 OHM 1% 1/16W 100ppm 0402", Mfr="Stackpole Electronics", MfrNo=RMCF0402FT330R
R420 R421 R422 R423: "(-55 to 155 DegC AEC) RES 5.6K OHM 1% 1/16W 100ppm 0402", Mfr=Yageo, MfrNo=RC0402FR-075K6L, Supplier Part Number 1=311-5.6KLRCT-ND
R461 R462: "(-55 to 155 DegC) RES SMD 22 OHM 1% 1/16W 0402", Mfr=Murata, MfrNo=GRT155R71H104KE01D
RA1 RA15 RA17 RA29 RA35 RA37 RA41: "(-55 to 125 DegC) RES ARRAY 2 RES 22 OHM 5% 0606 200ppm", Mfr=Panasonic, MfrNo=EXB-34V220JV, Supplier Part Number 1=Y8220CT-ND
RA3 RA8 RA9 RA10: "(-55 to 125 DegC) RES ARRAY 4 RES 10K 1% 200ppm 1206", Mfr=Yageo, MfrNo=TC164-FR-0710KL, Supplier Part Number 1=RAVF164DJT10K0CT-ND
RA4 RA5 RA6: "RES ARRAY 2 RES 0606"
RA7 RA11 RA14 RA16 RA18 RA19 RA20 RA21 RA22 RA23 RA24 RA25 RA26 RA27 RA28 RA30 RA31 RA32 RA33 RA34 RA36 RA38 RA39 RA40 RA45: "(-55 to 125 DegC) RES ARRAY 4 RES 22 OHM 0804 +/-300ppm SMD", Mfr=Bourns, MfrNo=CAT10A-220J4LF, Supplier Part Number 1=118-CAT10A-220J4LFCT-ND
S1 S2 S3 S4: library part "2693-Slide Switch-DPDT VERT SMT", "(-20 to 70 DegC) Slide switch DPDT 12V 100mA SMT 9.1x6.9mm VERT SLIDE", Mfr="Same Sky (CUI)", Supplier Part Number 1=2223-SLW-913535-2A-SMTCT-ND
U1 U104: library part 1666-MCP1799, "(-40 to 150 DegC) IC REG LINEAR LDO Vin: 45Vmax Vout:5V fixed 80mA SOT223-3", Mfr=Microchip, MfrNo=MCP1799T-5002H/DB, Supplier Part Number 1=150-MCP1799T-5002H/DBCT-ND
U2: library part 2224-LTC4368IDD-2#PBF, "(-40 to 85 DegC AEC) IC SURGE SUPPRESSION ADJ 2.5-60V OVERVOLTAGE/UNDERVOLTAGE/OVERCURRENT PROTECT 10DFN", Mfr="Analog Devices / Linear Technology", Supplier Part Number 1=584-LTC4368IDD2PBF
U3 U9 U10 U11 U19 U57 U81 U83 U88: library part 0972-PCA9306DCT, "(-40 to 85 DegC) IC TRANSLTR BIDIRECTIONAL I2C SM8", Mfr="Texas Instruments", MfrNo=PCA9306DCTR, Supplier Part Number 1=296-18509-1-ND
U4: library part 0966-INA226AIDGSR, "(-40 to 125 DegC) IC MONITOR PWR/CURR BIDIR 10MSOP I2C Vos:10uV max, 0.1%Gain Err max, 2.7-5.5Vcc, 0-36V", Mfr="Texas Instruments", MfrNo=INA226AIDGSR, Supplier Part Number 1=296-29034-1-ND
U5: library part 1619-TPS62823, "(-40 to 125 DegC) IC  IC REG BUCK ADJ 2.2MHz Vin:2.4-5.5V Io:3A Sync 8-VFDFN 8VSON-HR", Mfr="Texas Instruments", Supplier Part Number 1=296-50425-1-ND
U6: library part 1815-AOZ2261AQI-15, "(-40 to 85 DegC) 8A Syncronous Buck Regulator (Auto Restart), QFN4x4-22L, 4-28V", Mfr="Alpha & Omega Semiconductor", Supplier Part Number 1=785-1930-1-ND
U7: library part 2218-TPS61089RNRR, "(-40 to 85 DegC) IC REG BOOST ADJ 7A SYNC 20VQFN Vin:2.7-12V, Vout:4.5-12.6V 11VQFN", Mfr="Texas Instruments", Supplier Part Number 1=296-47295-1-ND
U8: library part 2192-LTC2954CTS8-2#TRMPBF, "(0 to 70 DegC) IC PB ON/OFF CONTROLLER TSOT23-8", Mfr="Analog Devices / Linear Technology", Supplier Part Number 1=505-LTC2954CTS8-2#TRMPBFCT-ND
U12 U17 U18 U42: library part 0740-TPD4E001, "(-40 to 125 DegC AEC) TVS DIODE 5.5VWM 16VC SOT-23-6", Mfr="Texas Instruments", MfrNo=TPD4E001QDBVRQ1, Supplier Part Number 1=296-39344-1-ND
U13: library part 0968-AP2127K, "(-40 to 85 DegC) IC REG LIN LDO POS ADJ 300MA (450 max) SOT23-5 2.5-6 Vin 0.3Vd@0.3A", Mfr="Diodes Incorporated", MfrNo=AP2127K-ADJTRG1, Supplier Part Number 1=AP2127K-ADJTRG1DICT-ND
U14: library part 1263-93LC56BT, "(-40 to 85 DegC) IC EEPROM 2KBit 128x16 SPI 2MHz SOT23-6 2.5-5.5V", Mfr=Microchip, Supplier Part Number 1=93LC56BT-I/OTCT-ND
U15: library part 0956-FT4232H, "(-40 to 85 DegC) IC USB HS QUAD UART/SYNC 64-LQFP", Mfr="FTDI, Future Technology Devices International Ltd", MfrNo=FT4232HL-REEL, Supplier Part Number 1=768-1026-2-ND
U16 U28 U29 U80: library part 1475-AP22653, "(-40 to 85 DegC) IC PWR SWITCH 3-5.5V EN-Active-High ENth:1.5V With-Discharge 65mohm typ ADJ 0.1-2.1A 6SSOP", Mfr=Diodes, Supplier Part Number 1=31-AP22653AW6-7CT-ND
U20 U23 U24 U30 U31 U32 U33 U34 U38 U39 U46 U47 U53 U84 U98 U99 U100: library part 1463-D3V3F4U10LP, "(-55 to 150 DegC) IC TVS DIODE 4ch Vrm:3.3V Vbr:6.2 Vcl:5V@16A 12KV/12KV 0.5pF 10-UFDFN 0.5mm", Mfr=Diodes, Supplier Part Number 1=D3V3F4U10LP-7DICT-ND
U21 U97: library part 2238-AP22615AWU-7, "(-40 to 85 DegC) IC PWR SWITCH 3-5.5V EN-Active-High ENth:1.2V With-Discharge 40mohm typ ADJ 0.4-4A TSOT-26", Mfr=Diodes, Supplier Part Number 1=AP22615AWU-7DICT-ND
U22: library part 1831-PTN5110, "(-40 to 85 DegC) IC USB Type-C CC Logic and port control DRP 16-HX2QFN 2.6x2.6", Mfr="NXP Semiconductors", Supplier Part Number 1=568-13797-1-ND
U25 U40: library part 2239-PESD15VL2BT,215, "(-65 to 150 DegC) TVS DIODE 2-CH 15VWM 44VC ESD:30KV TO236AB", Mfr=Nexperia, Supplier Part Number 1=1727-3813-1-ND
U26 U35 U36: library part 1467-AP2132BMP-2.5, "(-40 to 85 DegC) IC REG LDO LINEAR POS ADJ 5V 2A 8SO", Mfr=Diodes, Supplier Part Number 1=AP2132BMP-2.5TRG1DICT-ND
U27: library part 1643-USB5744, "(-40 to 85 DegC) IC 4 port USB3.2 HUB 56-VFQFN", Mfr=Microchip, Supplier Part Number 1=USB5744T-I/2GCT-ND
U37: library part 2243-DP83867ISRGZ, "(-40 to 85 DegC) 1G PHY Gigabit Ethernet Transceiver with SGMII QFN-48", Mfr="Texas Instruments", MfrNo=DP83867ISRGZR, Supplier Part Number 1=296-48906-1-ND
U41 U96: library part 2263-TMUXHS4212IRKSR, "(-40 to 105 DegC) IC SWITCH MULTIPLEXER 2:1 DPST, SPDT X 2 3.3V/1.8V 20VQFN", Mfr="Texas Instruments", Supplier Part Number 1=595-TMUXHS4212IRKSR
U43: library part 2248-D5V0M5B6LP16-7, "(-65 to 150 DegC) IC TVS DIODE 5ch Vrm:5V Vcl:10V@1A 6-UFDFN", Mfr=Diodes, Supplier Part Number 1=D5V0M5B6LP16-7DICT-ND
U44 U60 U61 U62 U64 U82 U87 U89: library part 1597-74AVC4T774, "(-40 to 125 DegC AEC) IC Translator 4ch BiDirer 0.8 to 3.6V 380MBps 16TSSOP", Mfr=Nexperia, Supplier Part Number 1=1727-74AVC4T774PW-Q100JCT-ND
U45: library part 2009-74LVC1G14SE-7, "(-40 to 125 DegC) IC INVERTER SCHMITT 1CH 1IN 1.65-5.5V SOT353", Mfr=Diodes, Supplier Part Number 1=74LVC1G14SE-7CT-ND
U48 U49 U69 U70: library part 1620-TCAN1044VDRQ1, "(-40 to 125 DegC) IC TXRX CAN FD 8MBPS Vio:1.8-5V Standby 8SOIC", Mfr="Texas Instruments", Supplier Part Number 1=296-TCAN1044VDRQ1CT-ND
U50 U51 U71 U72: library part 1564-ESDCAN06-2BWY, "(-55 to 175 DegC AEC) TVS DIODE CAN 2-ch 35V Vcl: 59Vmax, 8/20:3A, ESD:30KV air,30KV cont, 15pF, SOT323", Mfr=STMicroelectronics, Supplier Part Number 1=497-17304-1-ND
U52: library part 1498-WM8904, "(-40 to 85 DegC) IC AUDIO CODEC STEREO 32QFN", Mfr="Cirrus Logic", Supplier Part Number 1=598-2437-1-ND
U54: library part 1853-TMP1075DSGR, "(-55 to 125 DegC) IC Temp Sensor I2C 1.7-5.5V WSON8", Mfr="Texas Instruments", Supplier Part Number 1=296-TMP1075DSGRCT-ND
U55: library part 0905-M24C02, "(-40 to 85 DegC) IC EEPROM 2KBIT (256B) 400KHZ 8TSSOP 1.7-5.5V adr 0x50", Mfr=STMicroelectronics, Supplier Part Number 1=497-15746-1-ND
U56: library part 2211-MX25U25645GXDI00, "(-40 to 85 DegC) IC FLASH 256MBIT SPI/QU 1.65-2V 24TBGA", Mfr=Macronix, Supplier Part Number 1=1092-1243-ND
U58: library part 2219-AMC6821SDBQR, "(-40 to 125 DegC) IC TEMP MONTR/PWM FANCTRL 3.3-5V, I2C 16SSOP", Mfr="Texas Instruments", Supplier Part Number 1=595-AMC6821SDBQR
U59: library part 1847B-TMUX1574, "(-40 to 125 DegC) IC Protected Analog SW 4CH-DPDT (4 Switches), 1.5-5.5V, R:2ohm, 4.5ohm max, 2GHz 7pF 1.8Vc with pull down SOT23-16 4.2x2", Mfr="Texas Instruments", Supplier Part Number 1=296-TMUX1574DYYRCT-ND
U63: library part 1864-74AUP1G08GW, "(-40 to 125 DegC) IC GATE AND 1CH 2-INP 0.8-3.6V 5-TSSOP", Mfr=Nexperia, Supplier Part Number 1=771-74AUP1G08GW-G
U65 U66: library part 2065-UCC12040DVER, "(-40 to 125 DegC) IC Isolated DC DC Converter-Output 3.3V, 5V 140mA, 4.5V-5.5V Input", Mfr="Texas Instruments", Supplier Part Number 1=595-UCC12040DVER
U67 U68: library part 2198-ISO6721RBDR, "(-40 to 125 DegC) IC DGTL ISO GENERAL-PURPOSE, DUAL-CHANNEL, 1x In, 1x Out 1.71-5.5V", Mfr="Texas Instruments", Supplier Part Number 1=595-ISO6721RBDR
U73: library part 2194-LM25145RGYR, "(-40 to 125 DegC) IC REG BUCK 6-42V INPUT 20VFQFN 1MHz", Mfr="Texas Instruments", Supplier Part Number 1=595-LM25145RGYR
U74: library part 0236-LM2901, "(-40 to 125 DegC) IC COMPARATOR QUAD LP 14-TSSOP 2-30V OC Iq:1.3mAtyp 2.5mAmax Vos:1mVtyp 15mVmax Ib:25nAtyp 400nAmax", Mfr=ST, MfrNo=LM2901PT, Supplier Part Number 1=497-6454-1-ND
U75: library part 2216-CYPD3177-24LQXQ, "(-40 to 125 DegC) IC USB Type C PMIC 20V/5A Max 24-QFN (4x4)", Mfr="Infineon Technologies", Supplier Part Number 1=727-CYPD3177-24LQXQ
U76: library part 2215-SN65HVD01DRCR, "(-40 to 125 DegC) IC TRANSCEIVER HALF 1/1, 3V3 RS-485, 1.65V I/O, 10VSON", Mfr="Texas Instruments", Supplier Part Number 1=595-SN65HVD01DRCR
U77: library part 2205-TRS3122ERGER, "(-40 to 85 DegC) IC TRANSCEIVER RS-232 2/2 24-VQFN (4x4)", Mfr="Texas Instruments", Supplier Part Number 1=296-47305-2-ND
U78 U79: library part 2516-T3902, "(-40 to 85 DegC) IC MIC Bot Port PDM 3.5x2.6mm 1.65-3.63V", Mfr="TDK InvenSense", Supplier Part Number 1=1428-MMICT390200012CT-ND
U85: library part 2678-TCA9543APWR, "(-40 to 85 DegC) IC I2C MUX BUS SWITCH 1:2 1.65-5.5V 400kHz", Mfr="Texas Instruments", Supplier Part Number 1=296-42157-1-ND
U86: library part 2737-AP2127K-1.8TRG1, "(-40 to 85 DegC) IC REG LIN LDO POS 1.8V 300MA (450 max) SOT23-5 2.5-6 Vin 0.3Vd@0.3A", Mfr=Diodes, Supplier Part Number 1=AP2127K-1.8TRG1DICT-ND
U95: library part 2212-TUSB321AIRWBR, "(-40 to 85 DegC) IC USB TYPE-C CC LOGIC W/ DIR PIN 12-XFQFN", Mfr="Texas Instruments", Supplier Part Number 1=296-43703-1-ND
X1 X3 X10 X11 X12 X13 X14 X15 X16 X18 X19 X21 X22 X23 X24 X25 X28 X29 X30 X31 X32 X33 X34 X41 X42 X43 X45 X46 X47 X50 X51 X52 X53 X54 X55 X56 X57 X63 X65 X68 X70 X71 X72 X73 X74 X75 X76 X80 X82 X83 X84 X85 X86 X90 X93 X94 X95 X96 X102 X104 X107 X108 X109 X110 X111 X112 X113 X114 X115: "TestPoint TH"
X2 X4 X5 X6 X7 X8 X9: library part 1468-TestPoint3, "(-40 to 85 DegC) Test Point Hook Black TH", Mfr="Keystone Electronics", MfrNo=5281
X17 X20 X27 X36 X37 X38 X39 X48 X49 X59 X60 X61 X62 X64 X66 X67 X69 X87 X89 X91 X92 X98 X99 X100 X101 X103 X105 X106: "TestPoint SMD"
XB1: library part 1664-Conn-BatHolder, "Battery Holder Coin 10mm SMD", Mfr="Keystone Electronics", Supplier Part Number 1=36-3030CT-ND
Y1: "(-40 to 85 DegC) CRYSTAL 12MHZ 10PF SMD +-30ppm +-20ppm 3.2x2.5mm Caps:16pF", Mfr="Abracon LLC", MfrNo=ABM8G-106-12.000MHZ-T, Supplier Part Number 1=535-14512-1-ND
Y2 Y3: "(-40 to 85 DegC) CRYSTAL 25.0MHZ 18PF SMD +-50ppm +-20ppm 3.2x2.5mm", Mfr="IQD Frequency Products", MfrNo=LFXTAL055299REEL, Supplier Part Number 1=1923-1305-1-ND

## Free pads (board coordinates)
  round 0.025 on Mech1: 1(113.423,76.375) 1(113.573,76.375) 1(113.923,75.875) 1(114.273,76.375)

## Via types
v1: diameter 0.6, hole 0.3, Top Layer to Bottom Layer, tented both sides, 2171 vias
v2: diameter 0.6, hole 0.3, Top Layer to Bottom Layer, 48 vias
v3: diameter 1, hole 0.5, Top Layer to Bottom Layer, tented both sides, 37 vias
v4: diameter 0.5, hole 0.2, Top Layer to Bottom Layer, tented both sides, 34 vias
v5: diameter 0.6, hole 0.3, Top Layer to Bottom Layer, tented bottom, 17 vias

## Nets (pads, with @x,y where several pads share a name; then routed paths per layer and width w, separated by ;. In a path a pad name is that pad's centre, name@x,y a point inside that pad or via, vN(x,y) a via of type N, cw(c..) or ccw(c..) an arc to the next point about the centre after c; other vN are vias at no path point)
1V0_ETH2: C154.2 C156.2 C158.2 C160.2 C164.2 C167.2 C170.1 C173.1 C176.1 C179.1 R170.2 U36.6 U37.6 U37.24 U37.31 U37.42 X57.1 | length 24.6
  Top Layer w0.25: C170.1@82.55,179.575 82.55,178.983 82.8,178.733 v1(82.8,178.675) ; v1@82.804,178.679 83.262,179.137 83.262,179.462 C158.2@83.375,179.575
  Top Layer w0.3: C156.2@78.175,174.9 78.7,174.9 78.925,175.125 v1(78.925,175.75) ; C179.1@78.175,175.75 v1(78.925,175.75) ; C167.2@78.175,176.65 78.7,176.65 78.75,176.6 78.925,176.425 v1(78.925,175.75) ; C176.1@82.065,171.858 82.069,171.854 82.796,171.854 v1(82.8,171.85) 82.781,171.869 82.781,172.203 C164.2@82.371,172.612 ; C160.2@87.175,171.65 v1(87.175,173.25)
  Top Layer w0.5: U36.6@80.93,163.167 R170.2@80.93,164.925 80.93,165.809 80.94,165.799 81.405,165.799 81.59,165.614 82.24,165.614 X57.1@82.393,165.461
  INT2_SIG w0.5: X57.1@82.405,165.457 84.885,167.936 84.885,169.243 82.8,171.328 v1(82.8,171.85)
  Bottom Layer w0.2: v1(78.925,175.75) U37.42@79.65,175.75 ; v1(82.8,171.85) U37.31@82.8,172.6 ; v1(82.8,178.675) U37.6@82.8,179.4 ; U37.24@86.45,173.25 v1(87.175,173.25)
1V2_UHUB: C102.2 C103.2 C107.2 C109.2 C112.2 C114.2 C116.2 C119.2 C122.2 C123.2 C125.1 C127.1 R129.2 R134.2 R136.2 U26.6 U27.5 U27.12 U27.15 U27.21 U27.28 U27.33 U27.43 U27.49 X45.1 | length 22.9
  Top Layer w0.2: 93.52,159.282 R134.2@93.52,158.23 R136.2@94.47,158.23 ; v1(95.401,163.493) U27.21@96.193,163.493 ; v1(96.193,159.993) U27.28@96.193,160.693 ; U27.15@96.193,165.893 v1(96.193,166.593) ; U27.12@97.794,166.694 v1(97.794,167.752) ; v1(98.594,158.965) U27.33@98.594,159.891 ; U27.5@100.594,166.694 100.596,166.696 100.596,167.603 v1(100.637,167.644) ; v1(102.993,160.15) 102.993,160.691 U27.43@102.995,160.693 ; U27.49@102.995,163.093 102.997,163.095 103.814,163.095 v1(103.837,163.118)
  Top Layer w0.5: U26.6@90.826,156.581 R129.2@90.826,158.381 C122.2@90.826,159.282 X45.1@92.236,159.282 93.52,159.282 95.482,159.282 v1(96.193,159.993)
  Bottom Layer w0.2: v1(96.193,159.993) C123.2@96.193,160.693 ; C114.2@96.905,167.1 C102.2@98.659,167.1 ; C109.2@97.794,167.1 v1(97.794,167.752) ; C112.2@98.576,159.64 98.585,159.631 98.585,158.974 v1(98.594,158.965) ; C127.1@102.275,160.175 102.287,160.163 102.98,160.163 v1(102.993,160.15) ; C103.2@103.1,163.118 v1(103.837,163.118)
  Bottom Layer w0.25: C107.2@100.637,166.9 v1(100.637,167.644)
